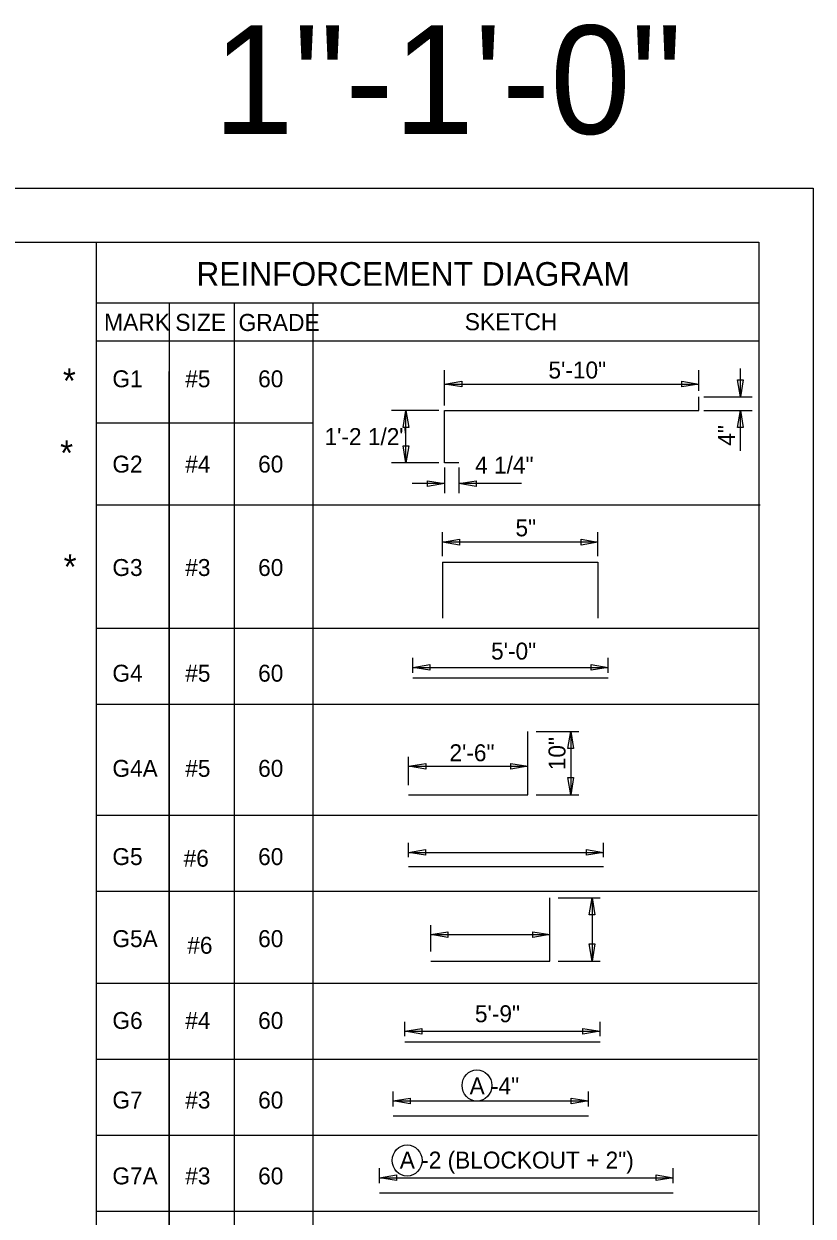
# Model space of a CAD drawing. Extents: x 0 to 34, y 0 to 23.5.
# Drawn here: x 26.72 to 34, y 12.51 to 23.51 of the extents above; entities that cross this region are included whole.
import ezdxf

# ---------------------------------------------------------------- set-up
doc = ezdxf.new("R2010")
doc.units = 0
for name, color, linetype in [('BORDER_ANNO_Cutsheet', 7, 'Continuous'), ('BRDG_ANNO_Anno-Sheet', 7, 'Continuous'), ('BRDG_ANNO_General-Notes', 7, 'Continuous'), ('BRDG_BASE_Obj-Line', 7, 'Continuous'), ('BRDG_BASE_Rebar', 7, 'Continuous'), ('Default', 7, 'Continuous')]:
    doc.layers.add(name, color=color, linetype=linetype)

# ---------------------------------------------------------------- blocks, each defined once
blk = doc.blocks.new('TERM')
at = {"layer": 'Default'}
for p, q in [((-1.6, -0.27), (-1.6, 0.27)), ((-1.6, 0.27), (0, 0)), ((0, 0), (-1.6, -0.27))]:
    blk.add_line(p, q, dxfattribs=at)

msp = doc.modelspace()

# ---------------------------------------------------------------- linework, layer by layer
at = {"layer": 'BORDER_ANNO_Cutsheet'}
msp.add_lwpolyline([(0, 22), (34, 22), (34, 0), (0, 0)], close=True, dxfattribs=at)
at = {"layer": 'BRDG_ANNO_Anno-Sheet'}
msp.add_lwpolyline([(1.5, 21.5), (33.5, 21.5), (33.5, 0.5), (1.5, 0.5)], close=True, dxfattribs=at)
at = {"layer": 'BRDG_ANNO_General-Notes'}
for p, q in [((30.601, 19.995), (30.601, 20.32)), ((32.945, 20.129), (32.945, 20.32)), ((33.329, 20.073), (33.329, 20.336)), ((30.601, 20.191), (30.759, 20.217)), ((30.601, 20.191), (32.945, 20.191)), ((30.759, 20.165), (30.601, 20.191)), ((30.759, 20.217), (30.759, 20.165)), ((32.788, 20.165), (32.788, 20.217)), ((32.788, 20.217), (32.945, 20.191)), ((32.945, 20.191), (32.788, 20.165)), ((33.303, 20.231), (33.356, 20.231)), ((33.329, 20.073), (33.303, 20.231)), ((33.356, 20.231), (33.329, 20.073)), ((32.992, 20.073), (33.439, 20.073)), ((30.547, 19.948), (30.112, 19.948)), ((30.218, 19.791), (30.244, 19.948)), ((30.244, 19.464), (30.244, 19.948)), ((30.244, 19.948), (30.271, 19.791)), ((32.992, 19.948), (33.439, 19.948)), ((33.303, 19.791), (33.329, 19.948)), ((33.329, 19.577), (33.329, 19.948)), ((33.329, 19.948), (33.356, 19.791)), ((30.271, 19.791), (30.218, 19.791)), ((33.356, 19.791), (33.303, 19.791)), ((30.218, 19.621), (30.271, 19.621)), ((30.244, 19.464), (30.218, 19.621)), ((30.271, 19.621), (30.244, 19.464)), ((30.547, 19.464), (30.112, 19.464)), ((30.601, 19.422), (30.601, 19.184)), ((30.734, 19.422), (30.734, 19.184)), ((30.601, 19.273), (30.302, 19.273)), ((30.444, 19.246), (30.444, 19.299)), ((30.444, 19.299), (30.601, 19.273)), ((30.601, 19.273), (30.444, 19.246)), ((30.734, 19.273), (30.892, 19.299)), ((31.311, 19.273), (30.734, 19.273)), ((30.892, 19.246), (30.734, 19.273)), ((30.892, 19.299), (30.892, 19.246)), ((30.583, 18.603), (30.583, 18.826)), ((32.016, 18.603), (32.016, 18.826)), ((32.016, 18.733), (30.583, 18.733)), ((30.309, 17.528), (30.309, 17.666)), ((30.309, 17.578), (30.466, 17.605)), ((30.466, 17.605), (30.466, 17.552)), ((31.952, 17.552), (31.952, 17.605)), ((31.952, 17.605), (32.11, 17.578)), ((32.11, 17.528), (32.11, 17.666)), ((30.309, 17.578), (32.11, 17.578)), ((30.466, 17.552), (30.309, 17.578)), ((32.11, 17.578), (31.952, 17.552)), ((31.445, 16.987), (31.839, 16.987)), ((31.738, 16.83), (31.764, 16.987)), ((31.764, 16.987), (31.764, 16.403)), ((31.764, 16.987), (31.791, 16.83)), ((30.27, 16.491), (30.27, 16.754)), ((31.791, 16.83), (31.738, 16.83)), ((30.27, 16.666), (30.427, 16.692)), ((30.27, 16.666), (31.37, 16.666)), ((30.427, 16.64), (30.27, 16.666)), ((30.427, 16.692), (30.427, 16.64)), ((31.213, 16.64), (31.213, 16.692)), ((31.213, 16.692), (31.37, 16.666)), ((31.37, 16.666), (31.213, 16.64)), ((31.738, 16.561), (31.791, 16.561)), ((31.764, 16.403), (31.738, 16.561)), ((31.791, 16.561), (31.764, 16.403)), ((31.445, 16.403), (31.839, 16.403)), ((30.267, 15.827), (30.267, 15.958)), ((32.068, 15.827), (32.068, 15.958)), ((30.267, 15.871), (30.424, 15.897)), ((30.267, 15.871), (32.068, 15.871)), ((30.424, 15.844), (30.267, 15.871)), ((30.424, 15.897), (30.424, 15.844)), ((31.91, 15.844), (31.91, 15.897)), ((31.91, 15.897), (32.068, 15.871)), ((32.068, 15.871), (31.91, 15.844)), ((31.648, 15.452), (32.037, 15.452)), ((31.936, 15.294), (31.962, 15.452)), ((31.962, 15.452), (31.962, 14.868)), ((31.962, 15.452), (31.988, 15.294)), ((31.988, 15.294), (31.936, 15.294)), ((30.473, 14.956), (30.473, 15.199)), ((31.573, 14.956), (31.573, 15.199)), ((30.473, 15.112), (30.63, 15.138)), ((30.473, 15.112), (31.573, 15.112)), ((30.63, 15.085), (30.473, 15.112)), ((30.63, 15.138), (30.63, 15.085)), ((31.416, 15.085), (31.416, 15.138)), ((31.416, 15.138), (31.573, 15.112)), ((31.573, 15.112), (31.416, 15.085)), ((31.936, 15.026), (31.988, 15.026)), ((31.962, 14.868), (31.936, 15.026)), ((31.988, 15.026), (31.962, 14.868)), ((31.648, 14.868), (32.037, 14.868)), ((30.234, 14.174), (30.234, 14.307)), ((32.035, 14.174), (32.035, 14.307)), ((30.234, 14.22), (30.392, 14.246)), ((30.234, 14.22), (32.035, 14.22)), ((30.392, 14.194), (30.234, 14.22)), ((30.392, 14.246), (30.392, 14.194)), ((31.877, 14.194), (31.877, 14.246)), ((31.877, 14.246), (32.035, 14.22)), ((32.035, 14.22), (31.877, 14.194)), ((30.126, 13.527), (30.126, 13.666)), ((31.927, 13.527), (31.927, 13.666)), ((30.126, 13.578), (30.283, 13.604)), ((30.126, 13.578), (31.927, 13.578)), ((30.283, 13.552), (30.126, 13.578)), ((30.283, 13.604), (30.283, 13.552)), ((31.769, 13.552), (31.769, 13.604)), ((31.769, 13.604), (31.927, 13.578)), ((31.927, 13.578), (31.769, 13.552)), ((30, 12.819), (30, 12.957)), ((30, 12.869), (30.157, 12.896)), ((30.157, 12.896), (30.157, 12.843)), ((32.551, 12.843), (32.551, 12.896)), ((32.551, 12.896), (32.708, 12.869)), ((32.708, 12.819), (32.708, 12.957)), ((30, 12.869), (32.708, 12.869)), ((30.157, 12.843), (30, 12.869)), ((32.708, 12.869), (32.551, 12.843))]:
    msp.add_line(p, q, dxfattribs=at)
for centre in [(30.9, 13.721), (30.256, 13.029)]:
    msp.add_ellipse(centre, major_axis=(0, 0.144), ratio=0.952381, dxfattribs=at)
at = {"layer": 'BRDG_BASE_Obj-Line'}
for p, q in [((27.387, 21.499), (27.387, 7.095)), ((27.387, 20.941), (33.506, 20.941)), ((28.06, 20.941), (28.06, 7.095)), ((28.66, 20.941), (28.66, 7.095)), ((29.386, 20.941), (29.386, 7.095)), ((27.387, 20.591), (33.5, 20.591)), ((28.059, 20.308), (28.059, 10.039)), ((27.387, 19.835), (29.386, 19.835)), ((27.387, 19.076), (33.512, 19.076)), ((27.387, 17.938), (33.494, 17.938)), ((27.387, 17.237), (33.506, 17.237)), ((27.387, 16.214), (33.488, 16.214)), ((27.387, 15.513), (33.488, 15.513)), ((27.387, 14.663), (33.488, 14.663)), ((27.387, 13.963), (33.488, 13.963)), ((27.387, 13.262), (33.488, 13.262)), ((27.387, 12.562), (33.488, 12.562))]:
    msp.add_line(p, q, dxfattribs=at)
at = {"layer": 'BRDG_BASE_Rebar'}
for p, q in [((30.583, 18.548), (32.016, 18.548)), ((30.583, 18.548), (30.583, 18.033)), ((32.016, 18.548), (32.016, 18.033)), ((30.309, 17.48), (32.11, 17.48)), ((31.37, 16.403), (31.37, 16.987)), ((30.27, 16.403), (31.37, 16.403)), ((30.267, 15.74), (32.068, 15.74)), ((31.573, 14.868), (31.573, 15.452)), ((30.473, 14.868), (31.573, 14.868)), ((30.234, 14.123), (32.035, 14.123)), ((30.126, 13.44), (31.927, 13.44)), ((30, 12.731), (32.708, 12.731))]:
    msp.add_line(p, q, dxfattribs=at)
msp.add_lwpolyline([(30.734, 19.464), (30.601, 19.464), (30.601, 19.948), (32.945, 19.948), (32.945, 20.073)], dxfattribs=at)

# ---------------------------------------------------------------- block references
at = {"layer": 'BRDG_ANNO_General-Notes', "xscale": 0.09765625, "yscale": 0.0976318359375, "rotation": 180}
msp.add_blockref('TERM', (30.583, 18.733), dxfattribs=at)
at = {"layer": 'BRDG_ANNO_General-Notes', "xscale": 0.09765625, "yscale": 0.0976318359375}
msp.add_blockref('TERM', (32.016, 18.733), dxfattribs=at)

# ---------------------------------------------------------------- texts
at = {"layer": 'BRDG_ANNO_Anno-Sheet'}
msp.add_text('1"-1\'-0"', height=1, dxfattribs=at).set_placement((28.467, 22.5))
at = {"layer": 'BRDG_ANNO_General-Notes'}
for s, height, p in [('REINFORCEMENT DIAGRAM', 0.21875, (28.312, 21.098)), ('MARK', 0.1576, (27.461, 20.684)), ('SIZE', 0.1576, (28.118, 20.682)), ('GRADE', 0.1575, (28.701, 20.681)), ('SKETCH', 0.1575, (30.787, 20.688)), ('5\'-10"', 0.1562, (31.559, 20.243)), ('*', 0.229, (27.081, 20.108)), ('G1', 0.1562, (27.538, 20.162)), ('#5', 0.1562, (28.21, 20.162)), ('60', 0.1562, (28.882, 20.162)), ('1\'-2 1/2"', 0.1562, (29.494, 19.629)), ('*', 0.229, (27.056, 19.442)), ('G2', 0.1562, (27.538, 19.375)), ('#4', 0.1562, (28.21, 19.375)), ('60', 0.1562, (28.882, 19.375)), ('4 1/4"', 0.1562, (30.883, 19.366)), ('5"', 0.1562, (31.255, 18.787)), ('*', 0.229, (27.088, 18.392)), ('G3', 0.1562, (27.538, 18.421)), ('#3', 0.1562, (28.21, 18.421)), ('60', 0.1562, (28.882, 18.421)), ('5\'-0"', 0.1562, (31.03, 17.65)), ('G4', 0.1562, (27.538, 17.446)), ('#5', 0.1562, (28.21, 17.446)), ('60', 0.1562, (28.882, 17.446)), ('2\'-6"', 0.1562, (30.646, 16.712)), ('G4A', 0.1562, (27.538, 16.568)), ('#5', 0.1562, (28.21, 16.568)), ('60', 0.1562, (28.882, 16.568)), ('G5', 0.1562, (27.538, 15.754)), ('#6', 0.1562, (28.195, 15.739)), ('60', 0.1562, (28.882, 15.754)), ('G5A', 0.1562, (27.538, 14.997)), ('#6', 0.1562, (28.229, 14.936)), ('60', 0.1562, (28.882, 14.997)), ('5\'-9"', 0.1562, (30.881, 14.304)), ('G6', 0.1562, (27.538, 14.242)), ('#4', 0.1562, (28.21, 14.242)), ('60', 0.1562, (28.882, 14.242)), ('A -4"', 0.1562, (30.832, 13.638)), ('G7', 0.1562, (27.538, 13.508)), ('#3', 0.1562, (28.21, 13.508)), ('60', 0.1562, (28.882, 13.508)), ('A -2 (BLOCKOUT + 2")', 0.15625, (30.188, 12.954)), ('G7A', 0.1562, (27.538, 12.808)), ('#3', 0.1562, (28.21, 12.808)), ('60', 0.1562, (28.882, 12.808))]:
    msp.add_text(s, height=height, dxfattribs=at).set_placement(p)
for s, p in [('4"', (33.278, 19.623)), ('10"', (31.716, 16.629))]:
    msp.add_text(s, height=0.1562, rotation=90, dxfattribs=at).set_placement(p)

doc.saveas('drawing.dxf')
